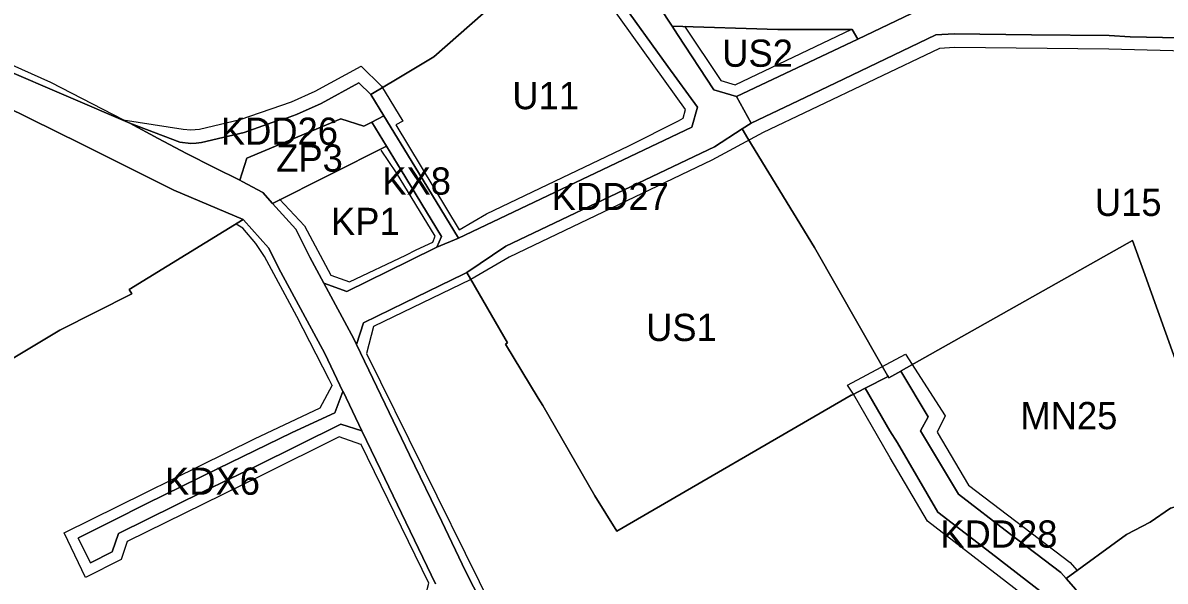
# Model space of a CAD drawing. Extents: x 7428841 to 7433518, y 5545054 to 5546840.
# Drawn here: x 7430661.7 to 7431082.1, y 5545800.1 to 5546005.4 of the extents above; entities that cross this region are included whole.
import ezdxf

# ---------------------------------------------------------------- set-up
doc = ezdxf.new("R2010")
doc.units = 0
for name, color, linetype in [('linie_rozgraniczajace', 7, 'Continuous'), ('linie_zabudowy_nieprzekraczalne', 7, 'Continuous'), ('oznaczenia_przeznaczen', 7, 'Continuous')]:
    doc.layers.add(name, color=color, linetype=linetype)

msp = doc.modelspace()

# ---------------------------------------------------------------- linework, layer by layer
at = {"layer": 'linie_rozgraniczajace'}
for points in [[(7430789.79, 5545978.99), (7430799.42, 5545984.75), (7430812.95, 5545992.86), (7430831.1, 5546008.76), (7430841.11, 5546017.57), (7430864.24, 5546038.02), (7430873.98, 5546024.3), (7430876.21, 5546021.22), (7430880.99, 5546014.41), (7430899.07, 5545989.37), (7430909.97, 5545974.33), (7430907.87, 5545967.06), (7430822.04, 5545926.18), (7430805.92, 5545952.58), (7430794.52, 5545971.24)], [(7430900.64, 5546004.12), (7430939.53, 5546002.93), (7430966.85, 5546002.97), (7430968.93, 5545999.38), (7430924.38, 5545978.24), (7430915.99, 5545980.71), (7430902.64, 5546001.07)], [(7430701.04, 5545968.47), (7430719.49, 5545961.45), (7430723.51, 5545961.01), (7430725.5, 5545961.2), (7430727.5, 5545961.39), (7430735.31, 5545963.22), (7430743.12, 5545965.05), (7430750, 5545967.49), (7430756.89, 5545969.93), (7430757.05, 5545969.69), (7430762.44, 5545971.64), (7430771.54, 5545975.75), (7430785.4, 5545983.3), (7430789.79, 5545978.99), (7430794.52, 5545971.24), (7430790.08, 5545968.92), (7430787.15, 5545967.39), (7430778.78, 5545970.1), (7430744.09, 5545955.64), (7430741.57, 5545947.54), (7430732.16, 5545952.2), (7430721.88, 5545957.3), (7430711.46, 5545962.88)], [(7430741.57, 5545947.54), (7430744.09, 5545955.64), (7430778.78, 5545970.1), (7430787.15, 5545967.39), (7430790.08, 5545968.92), (7430795.49, 5545960.08), (7430753.62, 5545938.98), (7430750.07, 5545943.02), (7430742.44, 5545947.11)], [(7430790.08, 5545968.92), (7430794.52, 5545971.24), (7430805.92, 5545952.58), (7430822.04, 5545926.18), (7430814.11, 5545922.89), (7430815.82, 5545926.89), (7430800.9, 5545951.25), (7430795.49, 5545960.08)], [(7430825.06, 5545913.56), (7430839.39, 5545923.29), (7430877.82, 5545941.53), (7430916.26, 5545959.78), (7430926.45, 5545966.44), (7430928.49, 5545962.9), (7430953.02, 5545922.75), (7430977.41, 5545880.08), (7430979.89, 5545875.75), (7430980.14, 5545875.34), (7430971.66, 5545871.04), (7430966.75, 5545868.55), (7430966.55, 5545868.46), (7430880.32, 5545818.51), (7430872.17, 5545831.47), (7430853.1, 5545864.75), (7430851.36, 5545867.36), (7430839.33, 5545887.3), (7430840.11, 5545887.74)], [(7430753.62, 5545938.98), (7430795.49, 5545960.08), (7430800.9, 5545951.25), (7430815.82, 5545926.89), (7430814.11, 5545922.89), (7430803.9, 5545917.89), (7430780.87, 5545906.62), (7430772.48, 5545909.68), (7430767.34, 5545919.23), (7430762.14, 5545929.51)], [(7430984.83, 5545877.34), (7430984.91, 5545877.39), (7431070.12, 5545925.35), (7431074.14, 5545914.17), (7431103.49, 5545832.51), (7431084.03, 5545826.97), (7431076.57, 5545821.79), (7431067.88, 5545817.29), (7431045.61, 5545801.14), (7431043.7, 5545803.28), (7431024.84, 5545817.68), (7431005.98, 5545832.07), (7430992.06, 5545855.41), (7430994.9, 5545860.48)], [(7430682.03, 5545815.92), (7430682.21, 5545816.01), (7430694.66, 5545822.31), (7430707.14, 5545828.53), (7430733.36, 5545841.39), (7430760.81, 5545854.72), (7430776.5, 5545861.98), (7430779.49, 5545869.88), (7430779.52, 5545869.81), (7430786.49, 5545855.34), (7430778.66, 5545857.9), (7430747.51, 5545842.42), (7430728.19, 5545833.05), (7430707.58, 5545822.97), (7430696.86, 5545817.6), (7430694.62, 5545810.89), (7430686.58, 5545806.86)], [(7431045.61, 5545801.14), (7431067.88, 5545817.29), (7431076.57, 5545821.79), (7431084.03, 5545826.97), (7431103.49, 5545832.51), (7431124.51, 5545838.5), (7431134.63, 5545844.49), (7431140.43, 5545848.13), (7431144.77, 5545850.84), (7431152.52, 5545821.69), (7431149.64, 5545813.17), (7431132.13, 5545804.74), (7431116.5, 5545795.25), (7431100.86, 5545785.75), (7431083.98, 5545772.74), (7431078.01, 5545768.14), (7431071.09, 5545769), (7431060.22, 5545783.81), (7431049.22, 5545797.1)]]:
    msp.add_lwpolyline(points, close=True, dxfattribs=at)
for points in [[(7430886.03, 5546026.33), (7430900.64, 5546004.12), (7430902.64, 5546001.07), (7430915.99, 5545980.71), (7430924.38, 5545978.24), (7430929.77, 5545968.5), (7430926.45, 5545966.44), (7430916.26, 5545959.78), (7430877.82, 5545941.53), (7430839.39, 5545923.29), (7430825.06, 5545913.56), (7430823.89, 5545912.99), (7430802.1, 5545902.43), (7430787.09, 5545895.14), (7430784.53, 5545887.07), (7430783.49, 5545889.22), (7430772.48, 5545909.68), (7430780.87, 5545906.62), (7430803.9, 5545917.89), (7430814.11, 5545922.89), (7430822.04, 5545926.18), (7430907.87, 5545967.06), (7430909.97, 5545974.33), (7430899.07, 5545989.37), (7430880.99, 5546014.41)], [(7430994.37, 5546011.45), (7430968.93, 5545999.38), (7430966.85, 5546002.97), (7430939.53, 5546002.93), (7430900.64, 5546004.12), (7430886.03, 5546026.33)], [(7431122.76, 5545999.17), (7431069.17, 5546000.25), (7431061.5, 5546000.73), (7431032.95, 5546001), (7431004.41, 5546001.28), (7430997.75, 5546000.91), (7430963.76, 5545984.7), (7430949.57, 5545977.92), (7430929.77, 5545968.5), (7430924.38, 5545978.24), (7430968.93, 5545999.38), (7430994.37, 5546011.45)], [(7430831.1, 5546008.76), (7430812.95, 5545992.86), (7430799.42, 5545984.75), (7430789.79, 5545978.99), (7430785.4, 5545983.3), (7430771.54, 5545975.75), (7430762.44, 5545971.64), (7430757.05, 5545969.69), (7430756.89, 5545969.93), (7430750, 5545967.49), (7430743.12, 5545965.05), (7430735.31, 5545963.22), (7430727.5, 5545961.39), (7430725.5, 5545961.2), (7430723.51, 5545961.01), (7430719.49, 5545961.45), (7430701.04, 5545968.47), (7430677.65, 5545978.55), (7430654.26, 5545988.63)], [(7431103.49, 5545832.51), (7431074.14, 5545914.17), (7431070.12, 5545925.35), (7430984.91, 5545877.39), (7430984.83, 5545877.34), (7430980.39, 5545874.92), (7430980.14, 5545875.34), (7430979.89, 5545875.75), (7430977.41, 5545880.08), (7430953.02, 5545922.75), (7430928.49, 5545962.9), (7430926.45, 5545966.44), (7430929.77, 5545968.5), (7430949.57, 5545977.92), (7430963.76, 5545984.7), (7430997.75, 5546000.91), (7431004.41, 5546001.28), (7431032.95, 5546001), (7431061.5, 5546000.73), (7431069.17, 5546000.25), (7431122.76, 5545999.17)], [(7430654.26, 5545988.63), (7430677.65, 5545978.55), (7430701.04, 5545968.47), (7430711.46, 5545962.88), (7430721.88, 5545957.3), (7430732.16, 5545952.2), (7430741.57, 5545947.54), (7430742.44, 5545947.11), (7430750.07, 5545943.02), (7430753.62, 5545938.98), (7430762.14, 5545929.51), (7430767.34, 5545919.23), (7430772.48, 5545909.68), (7430783.49, 5545889.22), (7430784.53, 5545887.07), (7430804.03, 5545846.54), (7430815.91, 5545822.08)], [(7430655.11, 5545974.8), (7430683.11, 5545960.86), (7430717.31, 5545943.83), (7430742.82, 5545933.05), (7430700.83, 5545907.4), (7430701.77, 5545905.73), (7430675.25, 5545892.35), (7430651.28, 5545878)], [(7430813.52, 5545799.14), (7430793.31, 5545841.15), (7430786.49, 5545855.34), (7430779.52, 5545869.81), (7430779.49, 5545869.88), (7430772.8, 5545883.77), (7430756.7, 5545913.68), (7430752.15, 5545922.69), (7430742.92, 5545933.01), (7430742.82, 5545933.05), (7430717.31, 5545943.83), (7430683.11, 5545960.86), (7430655.11, 5545974.8)], [(7430651.28, 5545878), (7430675.25, 5545892.35), (7430701.77, 5545905.73), (7430700.83, 5545907.4), (7430742.82, 5545933.05), (7430742.92, 5545933.01), (7430752.15, 5545922.69), (7430756.7, 5545913.68), (7430772.8, 5545883.77), (7430779.49, 5545869.88), (7430776.5, 5545861.98), (7430760.81, 5545854.72), (7430733.36, 5545841.39), (7430707.14, 5545828.53), (7430694.66, 5545822.31), (7430682.21, 5545816.01), (7430682.03, 5545815.92), (7430686.58, 5545806.86), (7430694.62, 5545810.89), (7430696.86, 5545817.6), (7430707.58, 5545822.97), (7430728.19, 5545833.05), (7430747.51, 5545842.42), (7430778.66, 5545857.9), (7430786.49, 5545855.34), (7430793.31, 5545841.15), (7430813.52, 5545799.14)], [(7430833.51, 5545786.31), (7430824.57, 5545803.85), (7430815.91, 5545822.08), (7430804.03, 5545846.54), (7430784.53, 5545887.07), (7430787.09, 5545895.14), (7430802.1, 5545902.43), (7430823.89, 5545912.99), (7430825.06, 5545913.56), (7430840.11, 5545887.74), (7430839.33, 5545887.3), (7430851.36, 5545867.36), (7430853.1, 5545864.75), (7430872.17, 5545831.47), (7430880.32, 5545818.51), (7430966.55, 5545868.46), (7430966.75, 5545868.55), (7430971.66, 5545871.04), (7430980.75, 5545855.37), (7430983.62, 5545851.02), (7430998.48, 5545825.55), (7431018.04, 5545810.46), (7431037.59, 5545795.36)], [(7431037.59, 5545795.36), (7431018.04, 5545810.46), (7430998.48, 5545825.55), (7430983.62, 5545851.02), (7430980.75, 5545855.37), (7430971.66, 5545871.04), (7430980.14, 5545875.34), (7430980.39, 5545874.92), (7430984.83, 5545877.34), (7430994.9, 5545860.48), (7430992.06, 5545855.41), (7431005.98, 5545832.07), (7431024.84, 5545817.68), (7431043.7, 5545803.28), (7431045.61, 5545801.14), (7431049.22, 5545797.1)], [(7430815.91, 5545822.08), (7430824.57, 5545803.85), (7430833.51, 5545786.31)]]:
    msp.add_lwpolyline(points, dxfattribs=at)
at = {"layer": 'linie_zabudowy_nieprzekraczalne'}
for points in [[(7430608.94, 5546083.87), (7430612.09, 5546073.25), (7430615.39, 5546060.23), (7430616.46, 5546050.13), (7430617.44, 5546029.27), (7430618.63, 5546019.05), (7430619.71, 5546015.32), (7430622.51, 5546010.32), (7430623.57, 5546008.72), (7430627.85, 5546003.61), (7430631.69, 5546000.75), (7430637.27, 5545998.13), (7430643.32, 5545996.34), (7430671.86, 5545983.62), (7430698.68, 5545969.71)], [(7430822.28, 5545929.32), (7430832.34, 5545935.19), (7430852.03, 5545944.56), (7430884.68, 5545960.16), (7430902.96, 5545969.34), (7430904.66, 5545970.36), (7430905.58, 5545973.57), (7430877.79, 5546012.1), (7430861.37, 5546035.16)], [(7430905.19, 5546004.13), (7430918.55, 5545984.14), (7430923.81, 5545982.63)], [(7430923.81, 5545982.63), (7430966.82, 5546003.03)], [(7431140.43, 5545848.13), (7431139.67, 5545850.58), (7431148.02, 5545902.54), (7431159.9, 5545933.07), (7431171.84, 5545963.53), (7431176.08, 5545990.51), (7431173.94, 5545993.14), (7431122.65, 5545994.12), (7431061.32, 5545995.73), (7431004.53, 5545996.27), (7430999.01, 5545995.97), (7430951.72, 5545973.41), (7430934.14, 5545965.04)], [(7430698.61, 5545969.7), (7430720.67, 5545966.35), (7430723.55, 5545966.03), (7430726.68, 5545966.33), (7430741.71, 5545969.86), (7430760.55, 5545976.28), (7430769.31, 5545980.23), (7430786.26, 5545989.47), (7430793.73, 5545982.12), (7430801.58, 5545969.28), (7430798.94, 5545967.94)], [(7430798.94, 5545967.94), (7430822.28, 5545929.32)], [(7430934.14, 5545965.04), (7430915.22, 5545954.85)], [(7430799.2, 5545950.2), (7430793.55, 5545958.52)], [(7430915.22, 5545954.85), (7430849.57, 5545923.47), (7430840.73, 5545919.25), (7430826.61, 5545911.05), (7430790.76, 5545893.69), (7430788.18, 5545883.83)], [(7430813.43, 5545926.96), (7430799.2, 5545950.2)], [(7430756.15, 5545940.55), (7430765.34, 5545930.78), (7430774.98, 5545912.62), (7430781.94, 5545910.16), (7430802.6, 5545919.97)], [(7430775.62, 5545871.85), (7430774.42, 5545874.29), (7430762.56, 5545897.46), (7430750.68, 5545919.44), (7430747.49, 5545924.26), (7430742.69, 5545929.89), (7430740.24, 5545931.36)], [(7430802.6, 5545919.97), (7430806.45, 5545921.88), (7430812.63, 5545924.78), (7430813.43, 5545926.96)], [(7430788.18, 5545883.83), (7430850.37, 5545758.09), (7430894.92, 5545672.75), (7430906.23, 5545651.94)], [(7430967.38, 5545868.84), (7430965.21, 5545872.16), (7430986.57, 5545883.6), (7431001.09, 5545860.91)], [(7430786.04, 5545850.41), (7430778.08, 5545853.2), (7430749.28, 5545838.83), (7430700.13, 5545814.74), (7430697.89, 5545808.06), (7430684.73, 5545801.46), (7430676.89, 5545817.85), (7430746.95, 5545852.45), (7430771.1, 5545863.82), (7430775.58, 5545872.01)], [(7431033.36, 5545792.32), (7430994.66, 5545822.18), (7430980.92, 5545845.44), (7430967.38, 5545868.84)], [(7431001.09, 5545860.91), (7430998.16, 5545854.9), (7431009.77, 5545835.46), (7431047.11, 5545806.97), (7431049.62, 5545804.18)], [(7430810.05, 5545795.21), (7430811.15, 5545799.44), (7430811.15, 5545799.44), (7430786.06, 5545850.56)]]:
    msp.add_lwpolyline(points, dxfattribs=at)

# ---------------------------------------------------------------- texts
at = {"layer": 'oznaczenia_przeznaczen'}
for s, p in [('US2', (7430919.07, 5545989.22)), ('U11', (7430841.83, 5545973.63)), ('KDD26', (7430734.57, 5545960.55)), ('ZP3', (7430754.93, 5545950.66)), ('KX8', (7430793.97, 5545942.23)), ('KDD27', (7430856.33, 5545936.53)), ('U15', (7431056.22, 5545934.38)), ('KP1', (7430775.1, 5545927.38)), ('US1', (7430891.05, 5545888.41)), ('MN25', (7431028.84, 5545856)), ('KDX6', (7430714.03, 5545831.9)), ('KDD28', (7430999.33, 5545812.47))]:
    msp.add_text(s, height=10, dxfattribs=at).set_placement(p)

doc.saveas('drawing.dxf')
